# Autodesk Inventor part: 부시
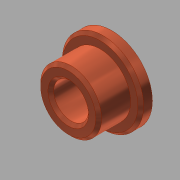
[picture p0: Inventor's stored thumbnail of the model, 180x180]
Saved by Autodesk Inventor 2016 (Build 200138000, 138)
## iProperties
Created: 2016-02
Part Number: 부시
Material: 강철, 연강
Document SubType Name: Modeling
Designer: test
Density: 1 g/cm^3
Appearance: 금속 1400F 열
Author: test
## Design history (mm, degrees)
sketch "스케치1"
  geometry: C1 r 14 at (0, 0); C2 r 10.5 at (0, 0); 1 further point
  constraints: 2 centre point, 2 coincident
  dimensions: "d0" = 28 diameter of C1; "d1" = 21 diameter of C2
extrude "돌출1" new body sketch "스케치1" distance "d2" = 4; taper "d3" = 0 deg
extrude "돌출2" join sketch "스케치1" distance "d4" = 11; taper "d5" = 0 deg
hole "구멍1" diameter "d8" = 12; stored, may be unused: countersink angle "d12" = 90 deg, drill point angle "d14" = 118 deg; dims "d6" = 10, "d7" = 10, "d9" = 6, "d10" = 4, "d11" = 2, "d13" = 8
chamfer "모따기1" distance "d15" = 1; stored, may be unused: second distance "d16" = 2, angle "d17" = 45 deg
chamfer "모따기2" distance "d18" = 1; stored, may be unused: second distance "d19" = 2, angle "d20" = 45 deg
node "솔리드1"
